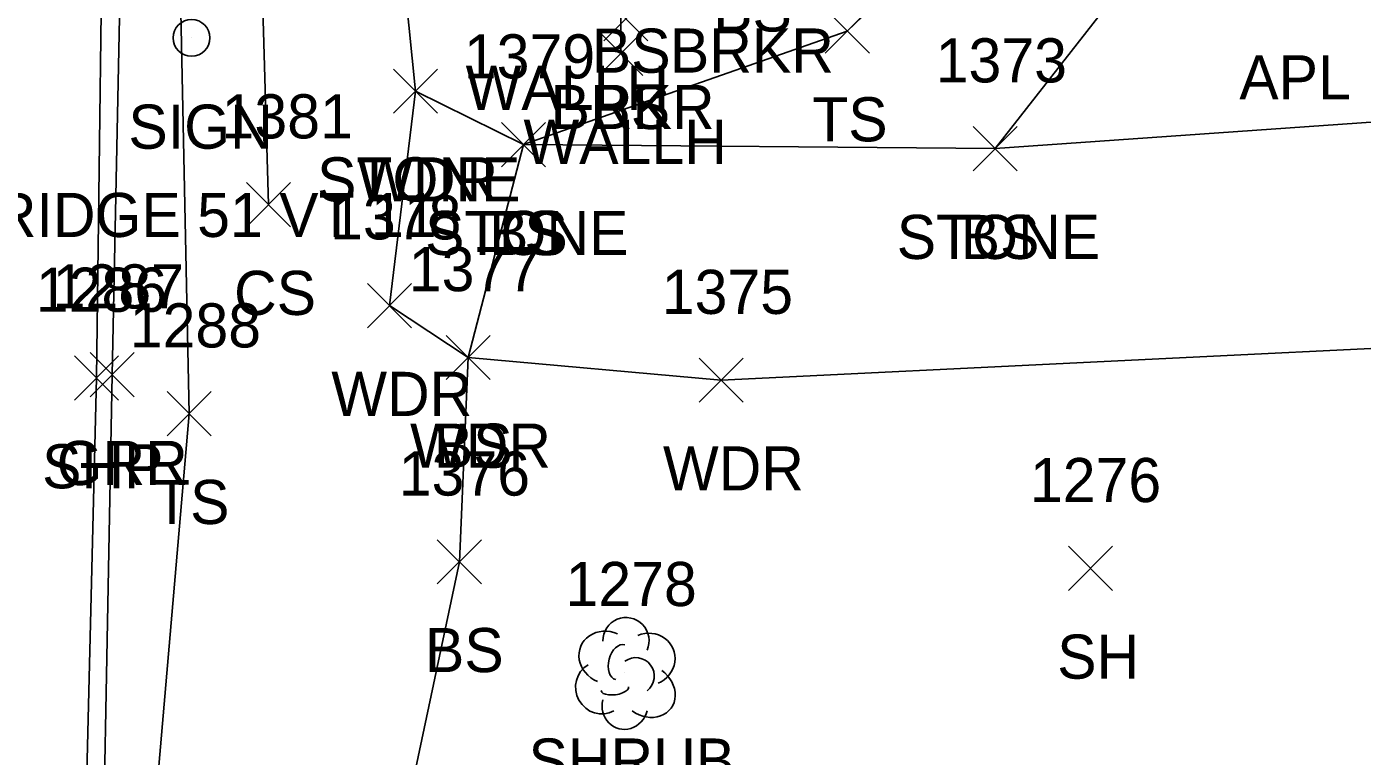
# Model space of a CAD drawing. Extents: x 1618262 to 1622220, y 273782 to 283685.
# Drawn here: x 1622080.2 to 1622140.8, y 282665.6 to 282698.6 of the extents above; entities that cross this region are included whole.
import ezdxf

# ---------------------------------------------------------------- set-up
doc = ezdxf.new("R2010")
doc.units = 0
for name, color, linetype in [('D_A', 7, 'Continuous'), ('D_TIC', 7, 'Continuous'), ('DHW', 7, 'Continuous'), ('L_A', 7, 'Continuous'), ('L_I', 7, 'Continuous'), ('L_TIC', 7, 'Continuous'), ('LASF', 7, 'Continuous'), ('LAWA', 7, 'Continuous'), ('LELB', 7, 'Continuous'), ('LSH', 7, 'Continuous'), ('M_A', 7, 'Continuous'), ('P_A', 7, 'Continuous'), ('P_I', 7, 'Continuous'), ('P_TIC', 7, 'Continuous'), ('PSP', 7, 'Continuous'), ('R_A', 7, 'Continuous'), ('R_I', 7, 'Continuous'), ('R_TIC', 7, 'Continuous'), ('RGR', 7, 'Continuous'), ('S_A', 7, 'Continuous'), ('S_C', 7, 'Continuous'), ('SSGN', 7, 'Continuous')]:
    doc.layers.add(name, color=color, linetype=linetype)

msp = doc.modelspace()

# ---------------------------------------------------------------- linework, layer by layer
at = {"layer": 'D_TIC'}
for points in [[(1622106.156, 282696.422), (1622108.156, 282698.422)], [(1622108.156, 282696.422), (1622106.156, 282698.422)]]:
    msp.add_lwpolyline(points, dxfattribs=at)
at = {"layer": 'DHW'}
msp.add_lwpolyline([(1622107.156, 282697.422), (1622107.12, 282704.906), (1622104.281, 282704.297), (1622104.534, 282699.869)], dxfattribs=at)
at = {"layer": 'L_TIC'}
for points in [[(1622106.385, 282698), (1622108.385, 282700)], [(1622108.385, 282698), (1622106.385, 282700)], [(1622106.385, 282698), (1622108.385, 282700)], [(1622108.385, 282698), (1622106.385, 282700)], [(1622116.42, 282697.441), (1622118.42, 282699.441)], [(1622118.42, 282697.441), (1622116.42, 282699.441)], [(1622096.849, 282694.719), (1622098.849, 282696.719)], [(1622098.849, 282694.719), (1622096.849, 282696.719)], [(1622096.849, 282694.719), (1622098.849, 282696.719)], [(1622098.849, 282694.719), (1622096.849, 282696.719)], [(1622101.742, 282692.292), (1622103.742, 282694.292)], [(1622103.742, 282692.292), (1622101.742, 282694.292)], [(1622101.742, 282692.292), (1622103.742, 282694.292)], [(1622103.742, 282692.292), (1622101.742, 282694.292)], [(1622101.742, 282692.292), (1622103.742, 282694.292)], [(1622103.742, 282692.292), (1622101.742, 282694.292)], [(1622123.116, 282692.112), (1622125.116, 282694.112)], [(1622125.116, 282692.112), (1622123.116, 282694.112)], [(1622123.116, 282692.112), (1622125.116, 282694.112)], [(1622125.116, 282692.112), (1622123.116, 282694.112)], [(1622090.189, 282689.575), (1622092.189, 282691.575)], [(1622092.189, 282689.575), (1622090.189, 282691.575)], [(1622095.674, 282684.998), (1622097.674, 282686.998)], [(1622097.674, 282684.998), (1622095.674, 282686.998)], [(1622099.241, 282682.651), (1622101.241, 282684.651)], [(1622101.241, 282682.651), (1622099.241, 282684.651)], [(1622099.241, 282682.651), (1622101.241, 282684.651)], [(1622101.241, 282682.651), (1622099.241, 282684.651)], [(1622110.705, 282681.621), (1622112.705, 282683.621)], [(1622112.705, 282681.621), (1622110.705, 282683.621)], [(1622086.596, 282680.102), (1622088.596, 282682.102)], [(1622088.596, 282680.102), (1622086.596, 282682.102)], [(1622098.84, 282673.39), (1622100.84, 282675.39)], [(1622100.84, 282673.39), (1622098.84, 282675.39)], [(1622127.442, 282673.094), (1622129.442, 282675.094)], [(1622129.442, 282673.094), (1622127.442, 282675.094)]]:
    msp.add_lwpolyline(points, dxfattribs=at)
at = {"layer": 'LASF'}
msp.add_lwpolyline([(1622145.163, 282735.978), (1622143.678, 282720.136), (1622134.988, 282707.013), (1622124.116, 282693.112), (1622102.742, 282693.292), (1622097.849, 282695.719), (1622096.809, 282706.041), (1622095.152, 282712.05), (1622094.742, 282720.999), (1622098.882, 282731.605), (1622115.268, 282742.964)], dxfattribs=at)
at = {"layer": 'LAWA'}
msp.add_lwpolyline([(1622146.408, 282684.313), (1622111.705, 282682.621), (1622100.241, 282683.651), (1622096.674, 282685.998), (1622097.849, 282695.719)], dxfattribs=at)
at = {"layer": 'LELB'}
for points in [[(1622121.158, 282596.521), (1622112.16, 282596.839), (1622102.984, 282598.765), (1622094.202, 282601.848), (1622088.687, 282605.568), (1622085.727, 282618.96), (1622084.898, 282649.699), (1622087.596, 282681.102), (1622086.983, 282710.968), (1622088.16, 282744.854), (1622088.43, 282782.064), (1622089.473, 282801.31), (1622094.579, 282809.136), (1622103.227, 282816.892), (1622109.052, 282823.895), (1622118.477, 282854.453), (1622116.353, 282881.374), (1622111.854, 282914.537), (1622109.182, 282938.553)], [(1622091.189, 282690.575), (1622090.701, 282707.297), (1622092.692, 282721.617), (1622095.205, 282734.089), (1622093.371, 282753.634), (1622092.46, 282776.611), (1622095.588, 282800.789), (1622106.617, 282809.831), (1622119.286, 282825.775), (1622124.751, 282845.144)], [(1622157.901, 282795.316), (1622151.518, 282778.21), (1622146.295, 282745.577), (1622145.163, 282735.978), (1622131.784, 282716.638), (1622123.793, 282704.55), (1622117.42, 282698.441), (1622102.742, 282693.292)], [(1622151.504, 282695.042), (1622124.116, 282693.112)], [(1622099.84, 282674.39), (1622100.241, 282683.651), (1622102.742, 282693.292)], [(1622099.84, 282674.39), (1622094.56, 282649.447)]]:
    msp.add_lwpolyline(points, dxfattribs=at)
at = {"layer": 'LSH'}
msp.add_line((1622107.343, 282669.384), (1622107.343, 282669.384), dxfattribs=at)
msp.add_line((1622107.343, 282669.384), (1622107.343, 282669.384), dxfattribs=at)
msp.add_arc((1622107.39, 282670.818), 1.047, 335.52715, 180.95627, dxfattribs=at)
for centre, major_axis, ratio, start_param, end_param in [((1622106.551, 282670.05), (1.21, -0.512), 0.895232, 1.570796, 4.712389), ((1622108.384, 282669.967), (-1.141, -0.483), 0.949671, 1.570796, 4.712389), ((1622107.134, 282669.842), (-0.208, -0.792), 0.645439, 3.141593, 6.283185), ((1622107.843, 282669.217), (-0.5, 0.667), 0.989748, 3.141593, 6.283185), ((1622106.26, 282668.675), (0.584, -1.042), 0.959034, 3.141593, 6.283185), ((1622108.343, 282668.551), (-1.09, 0.792), 0.841452, 1.570796, 4.712389), ((1622106.885, 282668.634), (-0.625, -0.083), 0.423636, 0, 3.141593), ((1622107.343, 282667.884), (0.265, 1.061), 0.942809, 1.570796, 4.712389)]:
    msp.add_ellipse(centre, major_axis=major_axis, ratio=ratio, start_param=start_param, end_param=end_param, dxfattribs=at)
at = {"layer": 'P_TIC'}
for points in [[(1622082.395, 282681.719), (1622084.395, 282683.719)], [(1622084.395, 282681.719), (1622082.395, 282683.719)]]:
    msp.add_lwpolyline(points, dxfattribs=at)
at = {"layer": 'PSP'}
msp.add_lwpolyline([(1622063.899, 282356.417), (1622068.955, 282404.452), (1622072.02, 282437.728), (1622074.665, 282475.613), (1622076.635, 282501.43), (1622078.271, 282531.064), (1622079.381, 282546.297), (1622079.58, 282558.785), (1622081.734, 282610.733), (1622082.589, 282649.97), (1622083.395, 282682.719), (1622083.739, 282709.962), (1622083.621, 282744.119), (1622083.448, 282781.355), (1622083.165, 282811.548), (1622082.701, 282831.314), (1622081.46, 282858.351), (1622080.359, 282881.435), (1622078.26, 282910.946), (1622077.134, 282929.735), (1622076.71, 282935.514)], dxfattribs=at)
at = {"layer": 'R_TIC'}
for points in [[(1622083.103, 282681.868), (1622085.103, 282683.868)], [(1622085.103, 282681.868), (1622083.103, 282683.868)]]:
    msp.add_lwpolyline(points, dxfattribs=at)
at = {"layer": 'RGR'}
msp.add_lwpolyline([(1622085.58, 282605.247), (1622083.68, 282611.3), (1622082.779, 282619.397), (1622083.481, 282650.056), (1622084.103, 282682.868), (1622084.658, 282710.116), (1622084.362, 282744.316), (1622084.303, 282781.106), (1622084.959, 282794.061), (1622087.053, 282807.794)], dxfattribs=at)
at = {"layer": 'SSGN'}
msp.add_line((1622087.703, 282698.128), (1622087.703, 282698.128), dxfattribs=at)
msp.add_circle((1622087.703, 282698.128), 0.833, dxfattribs=at)

# ---------------------------------------------------------------- texts
at = {"layer": 'D_A'}
for p in [(1622100.125, 282694.869), (1622102.746, 282692.422)]:
    msp.add_text('WALLH', height=2, dxfattribs=at).set_placement(p)
at = {"layer": 'L_A'}
for s, p in [('BS', (1622111.341, 282698.419)), ('BS', (1622105.847, 282696.551)), ('BS', (1622105.847, 282696.551)), ('BRKR', (1622109.382, 282696.556)), ('BRKR', (1622103.976, 282694)), ('BS', (1622105.826, 282694)), ('TS', (1622115.829, 282693.441)), ('STONE', (1622093.392, 282690.719)), ('WDR', (1622095.211, 282690.719)), ('STONE', (1622098.286, 282688.292)), ('TS', (1622101.152, 282688.292)), ('BS', (1622101.183, 282688.292)), ('STONE', (1622119.66, 282688.112)), ('BS', (1622122.557, 282688.112)), ('CS', (1622089.63, 282685.575)), ('WDR', (1622094.037, 282680.998)), ('WDR', (1622097.604, 282678.651)), ('BS', (1622098.682, 282678.651)), ('WDR', (1622109.067, 282677.621)), ('TS', (1622086.005, 282676.102)), ('BS', (1622098.281, 282669.39)), ('SH', (1622126.93, 282669.094)), ('SHRUB', (1622102.973, 282664.384))]:
    msp.add_text(s, height=2, dxfattribs=at).set_placement(p)
at = {"layer": 'L_I'}
for s, p in [('1379', (1622100.042, 282696.292)), ('1379', (1622100.042, 282696.292)), ('1379', (1622100.042, 282696.292)), ('1373', (1622121.424, 282696.112)), ('1373', (1622121.424, 282696.112)), ('1381', (1622089.063, 282693.575)), ('1378', (1622093.982, 282688.998)), ('1377', (1622097.549, 282686.651)), ('1377', (1622097.549, 282686.651)), ('1375', (1622109.012, 282685.621)), ('1288', (1622084.903, 282684.102)), ('1376', (1622097.092, 282677.39)), ('1276', (1622125.694, 282677.094)), ('1278', (1622104.65, 282672.384))]:
    msp.add_text(s, height=2, dxfattribs=at).set_placement(p)
at = {"layer": 'M_A'}
msp.add_text('APL', height=2, dxfattribs=at).set_placement((1622135.182, 282695.34))
at = {"layer": 'P_A'}
msp.add_text('SHP', height=2, dxfattribs=at).set_placement((1622080.93, 282677.719))
at = {"layer": 'P_I'}
msp.add_text('1286', height=2, dxfattribs=at).set_placement((1622080.647, 282685.719))
at = {"layer": 'R_A'}
msp.add_text('GRR', height=2, dxfattribs=at).set_placement((1622081.591, 282677.868))
at = {"layer": 'R_I'}
msp.add_text('1287', height=2, dxfattribs=at).set_placement((1622081.41, 282685.868))
at = {"layer": 'S_A'}
msp.add_text('SIGN', height=2, dxfattribs=at).set_placement((1622084.841, 282693.108))
at = {"layer": 'S_C'}
msp.add_text('BRIDGE 51 VT 11', height=2, dxfattribs=at).set_placement((1622076.96, 282689.108))

doc.saveas('drawing.dxf')
